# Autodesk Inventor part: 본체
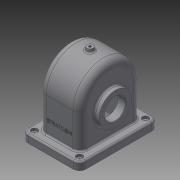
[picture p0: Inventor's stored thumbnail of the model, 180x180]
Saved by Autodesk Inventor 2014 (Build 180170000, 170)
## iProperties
Created: 2016-10
Part Number: 본체
Material: 일반
Document SubType Name: Modeling
Designer: USER
Density: 1 g/cm^3
Appearance: 기본값
Author: USER
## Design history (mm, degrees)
sketch "스케치1"
  geometry: L1 (-55, -75)-(55, -75); L2 (55, -75)-(55, 75); L3 (55, 75)-(-55, 75); L4 (-55, 75)-(-55, -75); L5 (-55, -75)-(55, 75); L6 (55, -75)-(-55, 75); 1 further point
  constraints: 12 end point, 2 midpoint, 2 parallel, 1 horizontal, 1 perpendicular
  dimensions: "d0" = 110 distance of L2.end L3.end; "d1" = 150 distance of L3.end L1.start
extrude "돌출1" new body sketch "스케치1" distance "d2" = 15; taper "d3" = 0 deg
fillet "모깎기1" dims "d4" = 12
hole "구멍1" diameter "d7" = 5; stored, may be unused: countersink angle "d11" = 90 deg, drill point angle "d13" = 118 deg; dims "d5" = 10, "d6" = 10, "d8" = 6, "d9" = 12, "d10" = 5, "d12" = 8
hole "구멍2" diameter "d16" = 5; stored, may be unused: countersink angle "d20" = 90 deg, drill point angle "d22" = 118 deg; dims "d14" = 10, "d15" = 10, "d17" = 6, "d18" = 12, "d19" = 5, "d21" = 8
hole "구멍3" diameter "d25" = 5; stored, may be unused: countersink angle "d29" = 90 deg, drill point angle "d31" = 118 deg; dims "d23" = 10, "d24" = 10, "d26" = 6, "d27" = 12, "d28" = 5, "d30" = 8
hole "구멍4" diameter "d34" = 5; stored, may be unused: countersink angle "d38" = 90 deg, drill point angle "d40" = 118 deg; dims "d32" = 10, "d33" = 10, "d35" = 6, "d36" = 12, "d37" = 5, "d39" = 8
sketch "스케치2"
  geometry: L1 (58, 15)-(58, 80); L2 (-58, 80)-(-58, 15); L3 (-58, 15)-(58, 15); L4 (63, 15)-(-63, 15) reference; A1 r 58 centre (0, 80) between (58, 80) and (-58, 80); 1 further point
  constraints: 6 end point, 2 point on circle, 2 tangent, 2 vertical, 1 centre point, 1 collinear, 1 perpendicular, 1 vertical alignment
  dimensions: "d41" = 80 distance of point (0, 0) A1.centre; "d42" = 58 radius of A1
extrude "돌출2" join sketch "스케치2" stored distance "d43" = 77; taper "d44" = 0 deg
sketch "스케치3"
  geometry: L1 (58, 15)-(58, 80) reference; L2 (-58, 80)-(-58, 15) reference; L3 (-52, 0)-(-52, 80); L4 (52, 80)-(52, 0); L5 (-63, 0)-(63, 0) reference; A1 r 58 centre (0, 80) between (58, 80) and (-58, 80) reference; A2 r 52 centre (0, 80) between (52, 80) and (-52, 80); 1 further point
  constraints: 4 end point, 2 point on circle, 2 point on line, 1 centre point
  dimensions: "d45" = 6 distance between parallel lines of L1 L4; "d46" = 6 radial gap between concentric circles of A1 A2; "d47" = 6 distance between parallel lines of L2 L3
extrude "돌출3" cut sketch "스케치3" stored distance "d48" = 67; taper "d49" = 0 deg
node "작업 평면1"
sketch "스케치5"
  geometry: L1 (0, -63)-(0, 63) reference; C1 r 31 at (-65, 0); A1 r 58 centre (-80, 0) between (-80, 58) and (-80, -58) reference; 1 further point
  constraints: 1 centre point, 1 horizontal alignment
  dimensions: "d54" = 65 distance from line of L1 C1.centre; "d55" = 62 diameter of C1
extrude "돌출5" join sketch "스케치5" distance "d56" = 10; taper "d57" = 0 deg
sketch "스케치6"
  geometry: L1 (0, 63)-(0, -63) reference; C1 r 37.5 at (65, 0); A1 r 58 centre (80, 0) between (80, -58) and (80, 58) reference; 1 further point
  constraints: 1 centre point, 1 horizontal alignment
  dimensions: "d58" = 65 distance from line of L1 C1.centre; "d59" = 75 diameter of C1
extrude "돌출6" join sketch "스케치6" distance "d60" = 5; taper "d61" = 0 deg
sketch "스케치7"
  geometry: L1 (33.5, 104.747)-(19.5, 93); L2 (19.5, 93)-(19.5, 65); L3 (19.5, 65)-(33.5, 65); L4 (33.5, 65)-(33.5, 104.747); L5 (33.5, 80)-(33.5, 132) reference; L6 (-33.5, 0)-(33.5, 0) reference; L7 (43.5, 27.5)-(43.5, 102.5) reference; 1 further point
  constraints: 8 end point, 2 perpendicular, 1 collinear, 1 vertical
  dimensions: "d62" = 65 distance between parallel lines of L6 L3; "d63" = 50 deg angle of L2 L1; "d64" = 28 distance of L1.end L2.end; "d65" = 24 distance between parallel lines of L2 L7
revolve "회전1" sketch "스케치7" stored, may be unused: angle "d66" = 90 deg
fillet "모깎기2" dims "d67" = 13
fillet "모깎기3" dims "d68" = 8
fillet "모깎기4" dims "d69" = 3
fillet "모깎기5" dims "d70" = 3
fillet "모깎기6" dims "d71" = 3
hole "구멍5" diameter "d74" = 40; stored, may be unused: countersink angle "d78" = 90 deg, drill point angle "d80" = 118 deg; dims "d72" = 10, "d73" = 10, "d75" = 6, "d76" = 12, "d77" = 5, "d79" = 8
chamfer "모따기1" distance "d81" = 1; stored, may be unused: second distance "d82" = 2, angle "d83" = 45 deg
node "작업 평면2"
sketch "스케치12"
  geometry: C1 r 6 at (0, 0); 1 further point
  constraints: 1 centre point, 1 coincident
  dimensions: "d85" = 12 diameter of C1
extrude "돌출7" join sketch "스케치12" stored distance "d86" = 5; taper "d87" = 10 deg
fillet "모깎기7" dims "d88" = 3
sketch "스케치13"
  geometry: 1 further point
sketch "스케치14"
  geometry: C1 r 31 at (0, 0) reference; 2 further points
  constraints: 1 horizontal alignment
  dimensions: "d89" = 26 distance of C1.centre point (-26, 0)
hole "구멍6" sketch "스케치14" at (-26, 0) diameter "d90" = 2.459; stored, may be unused: countersink angle "d94" = 90 deg, drill point angle "d96" = 118 deg; dims "d91" = 6, "d92" = 12, "d93" = 5, "d95" = 8
sketch "스케치15"
  geometry: C1 r 37.5 at (0, 0) reference; 2 further points
  constraints: 1 horizontal alignment
  dimensions: "d100" = 29 distance of C1.centre point (29, 0)
hole "구멍7" sketch "스케치15" at (29, 0) diameter "d101" = 2.459; stored, may be unused: countersink angle "d105" = 90 deg, drill point angle "d107" = 118 deg; dims "d102" = 6, "d103" = 12, "d104" = 5, "d106" = 8
hole "구멍8" diameter "d113" = 4.459; stored, may be unused: countersink angle "d117" = 90 deg, drill point angle "d119" = 120 deg; dims "d114" = 50, "d115" = 12, "d116" = 5, "d118" = 8, "d120" = 10, "d121" = 10
node "작업 평면3"
sketch "스케치19"
  geometry: L1 (-43, 0)-(43, 0) reference; L2 (-38.5, 80)-(-38.5, 18) reference; 2 further points
  constraints: 1 other
  dimensions: "d123" = 40 distance of point (0, 0) point (0, 40); "d124" = 38.5 distance from line of point (0, 40) L2
feature "엠보싱1" sketch "스케치19" dims "d125" = 0.5, "d126" = 0
node "솔리드1"
pattern_circular "원형 패턴1" dims angle "d98" = 360 deg
pattern_circular "원형 패턴2" dims angle "d109" = 360 deg
other parameters: "d50" = 144, "d84" = 144, "d122" = -102
